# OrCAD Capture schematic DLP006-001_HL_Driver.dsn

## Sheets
1 P01- Title Page
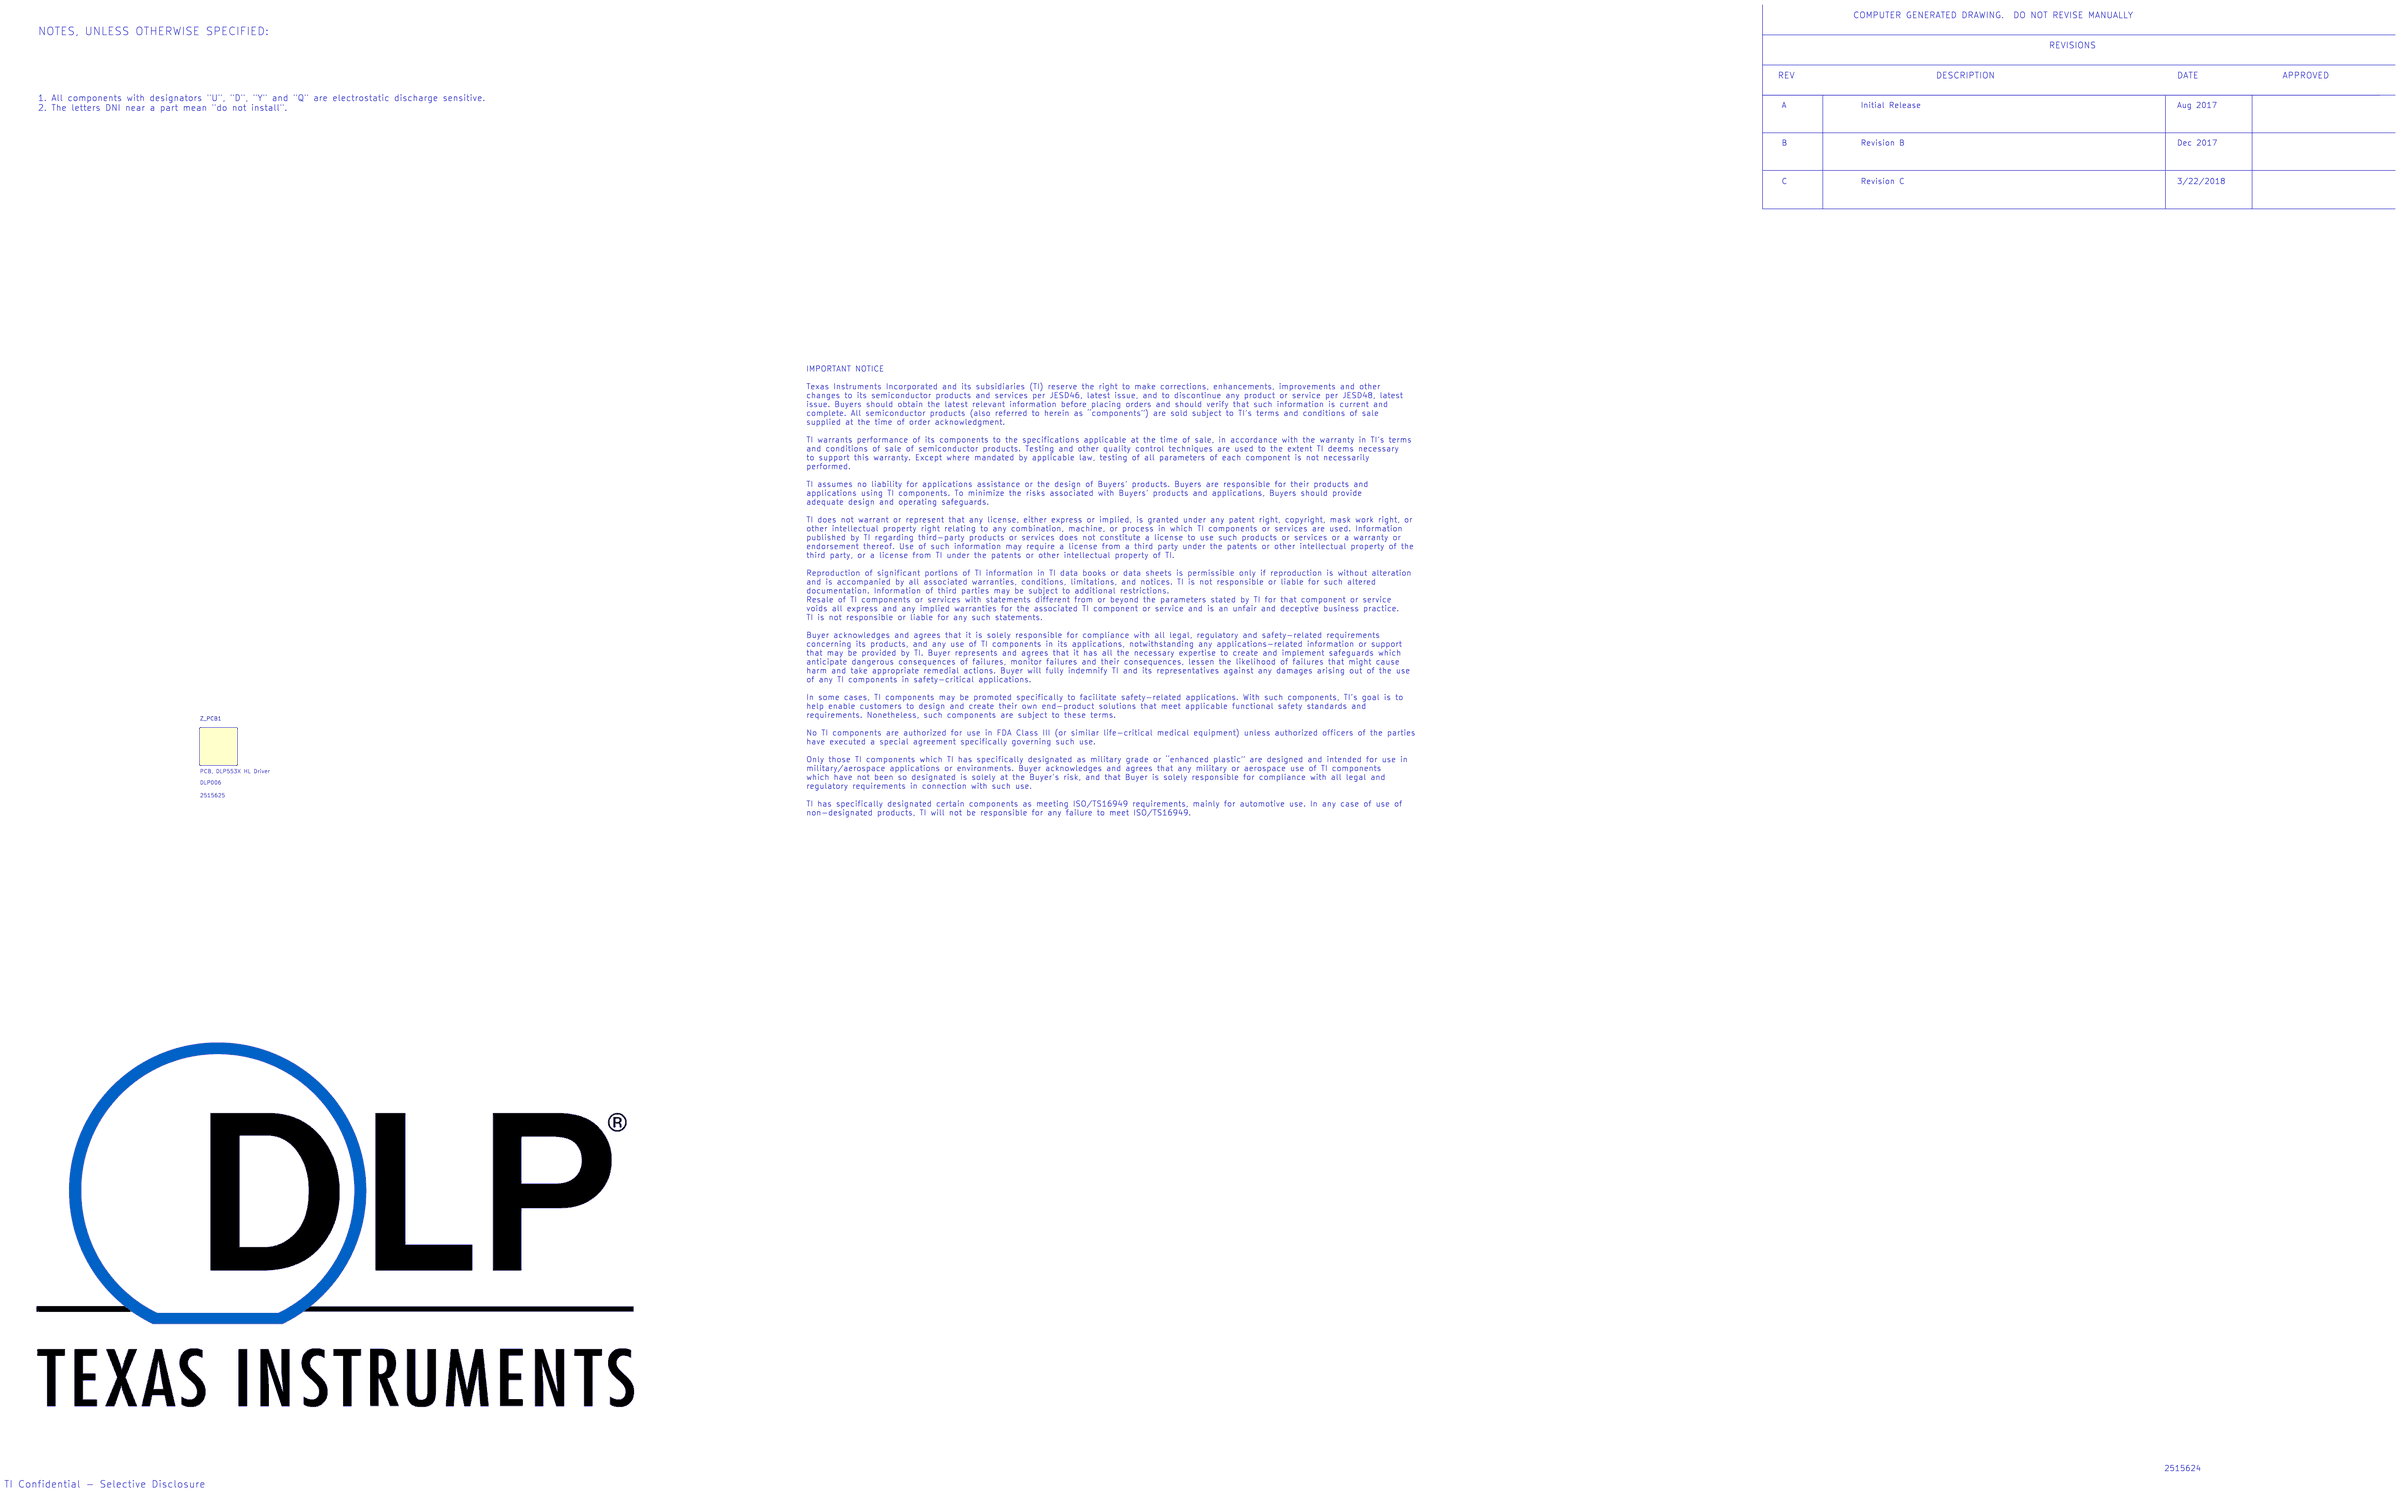
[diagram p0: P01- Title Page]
2 P02- Block Diagram: title: DLP5531-Q1 EVM Headlight Driver - DLP006; rev: C; note: 2515624
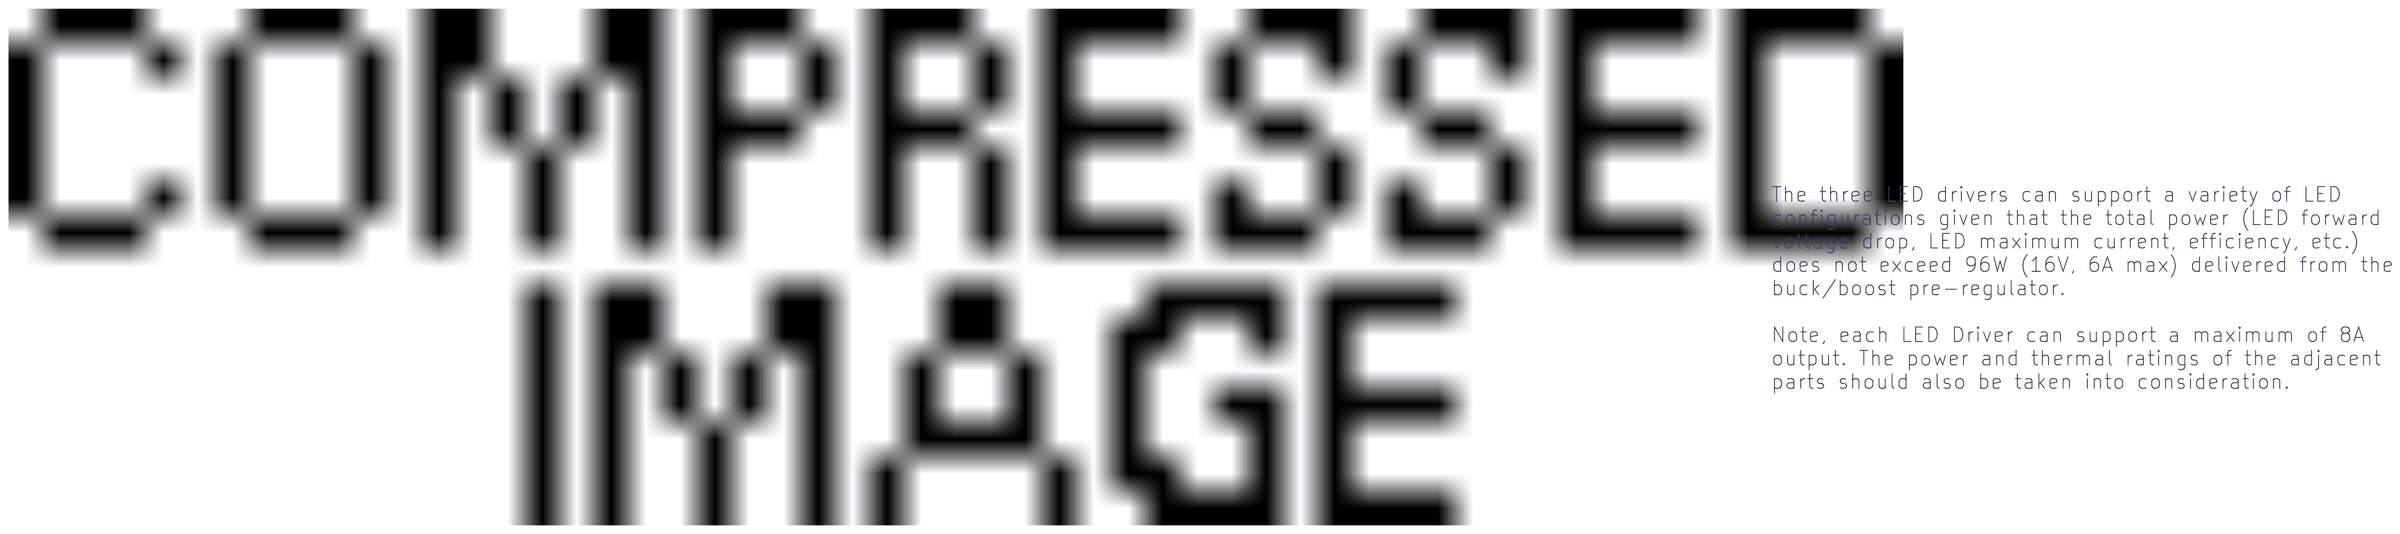
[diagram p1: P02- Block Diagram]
3 P03- LM5175 pre-regulator: size D; title: DLP5531-Q1 EVM Headlight Driver - DLP006; rev: C; note: 2515624
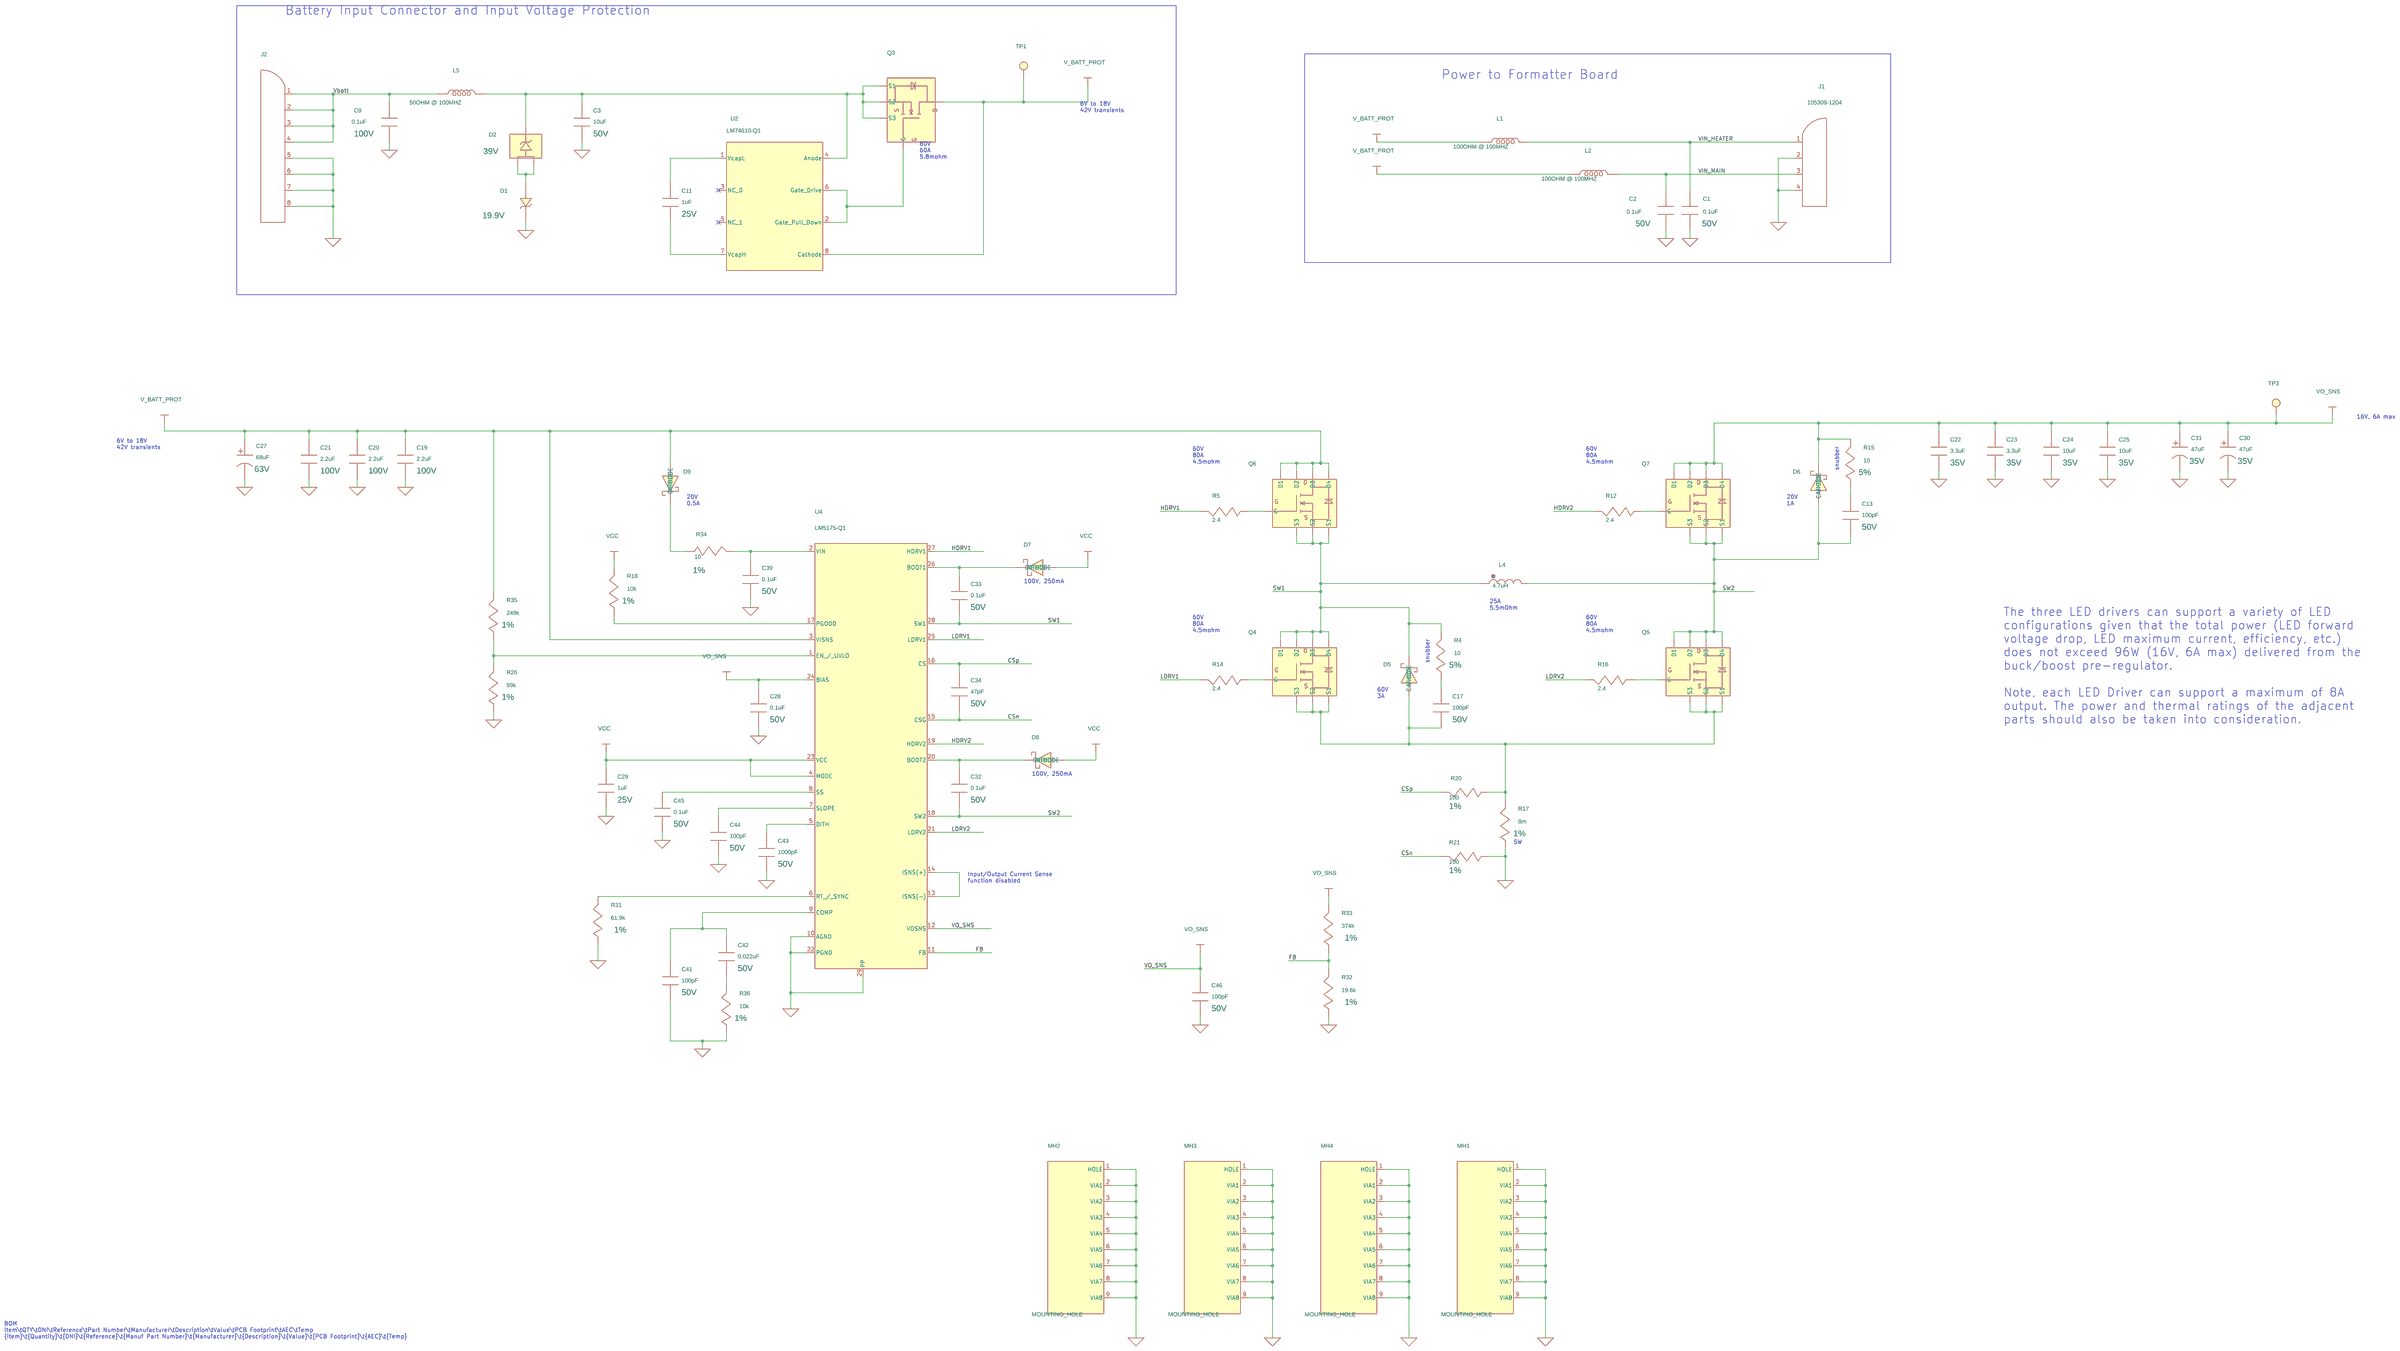
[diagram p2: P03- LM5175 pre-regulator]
4 P04- LM3409 LED drivers: size D; title: DLP5531-Q1 EVM Headlight Driver - DLP006; rev: C; note: 2515624
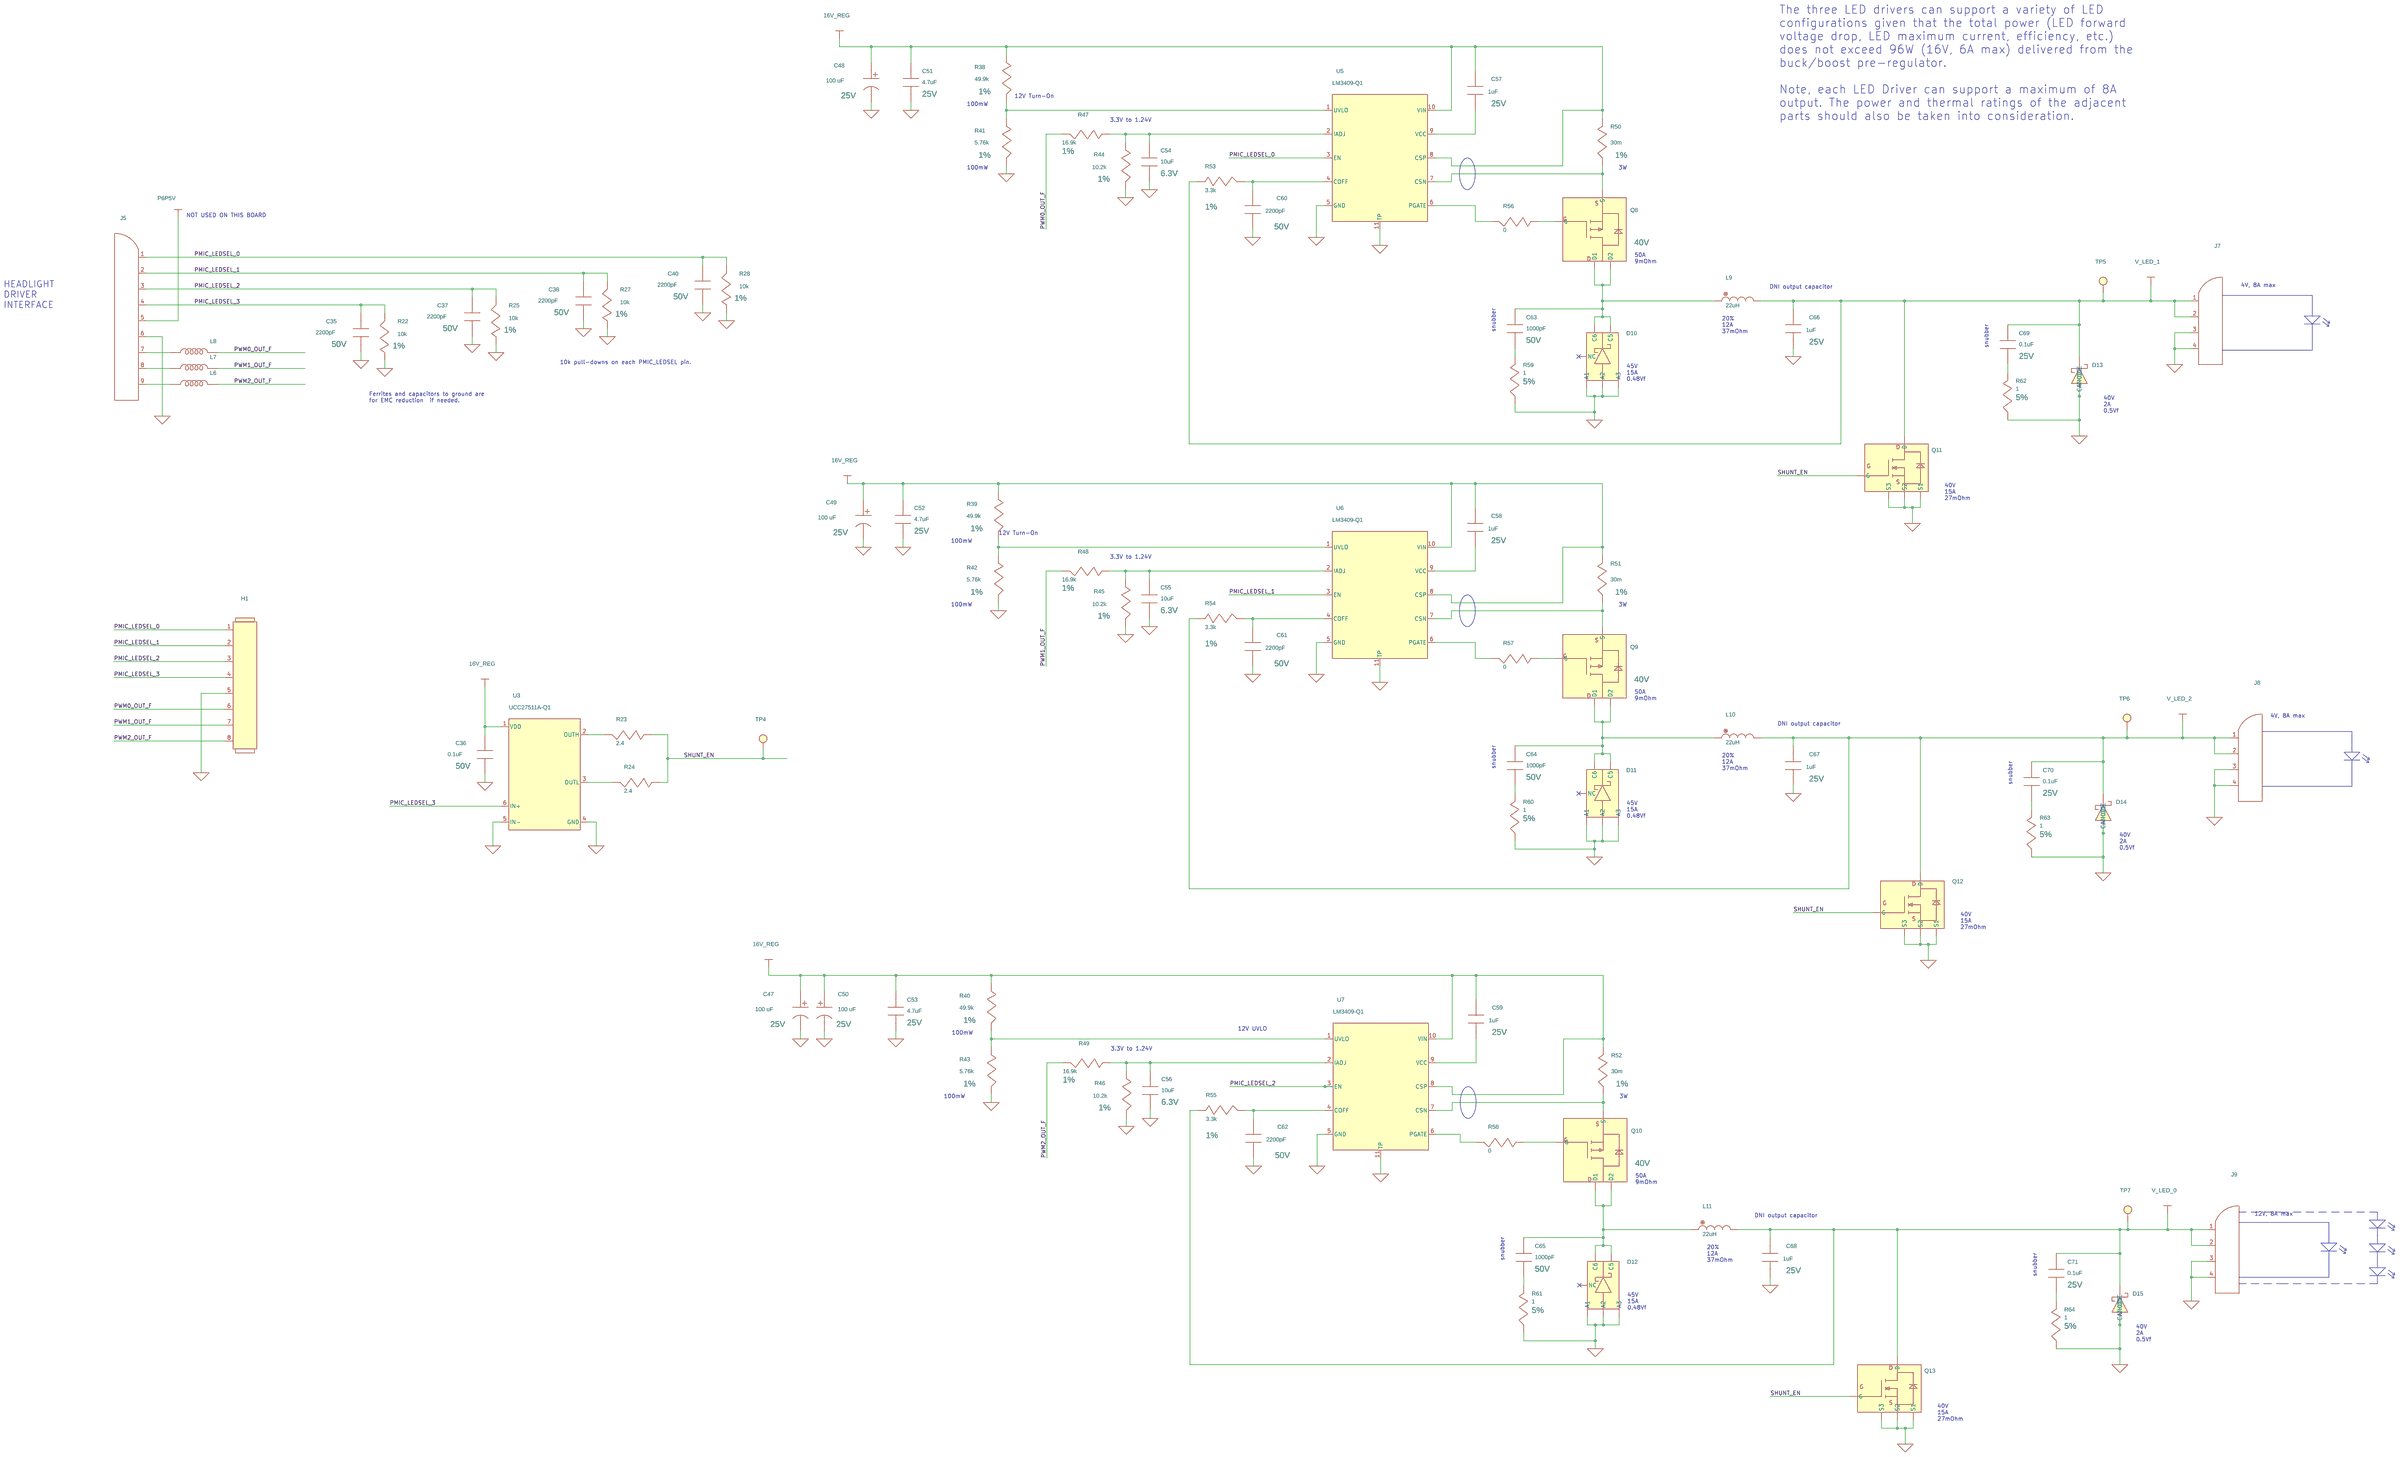
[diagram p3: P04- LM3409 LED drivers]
5 P05- LM25118 fan driver: size D; title: DLP5531-Q1 EVM Headlight Driver - DLP006; rev: C; note: 2515624
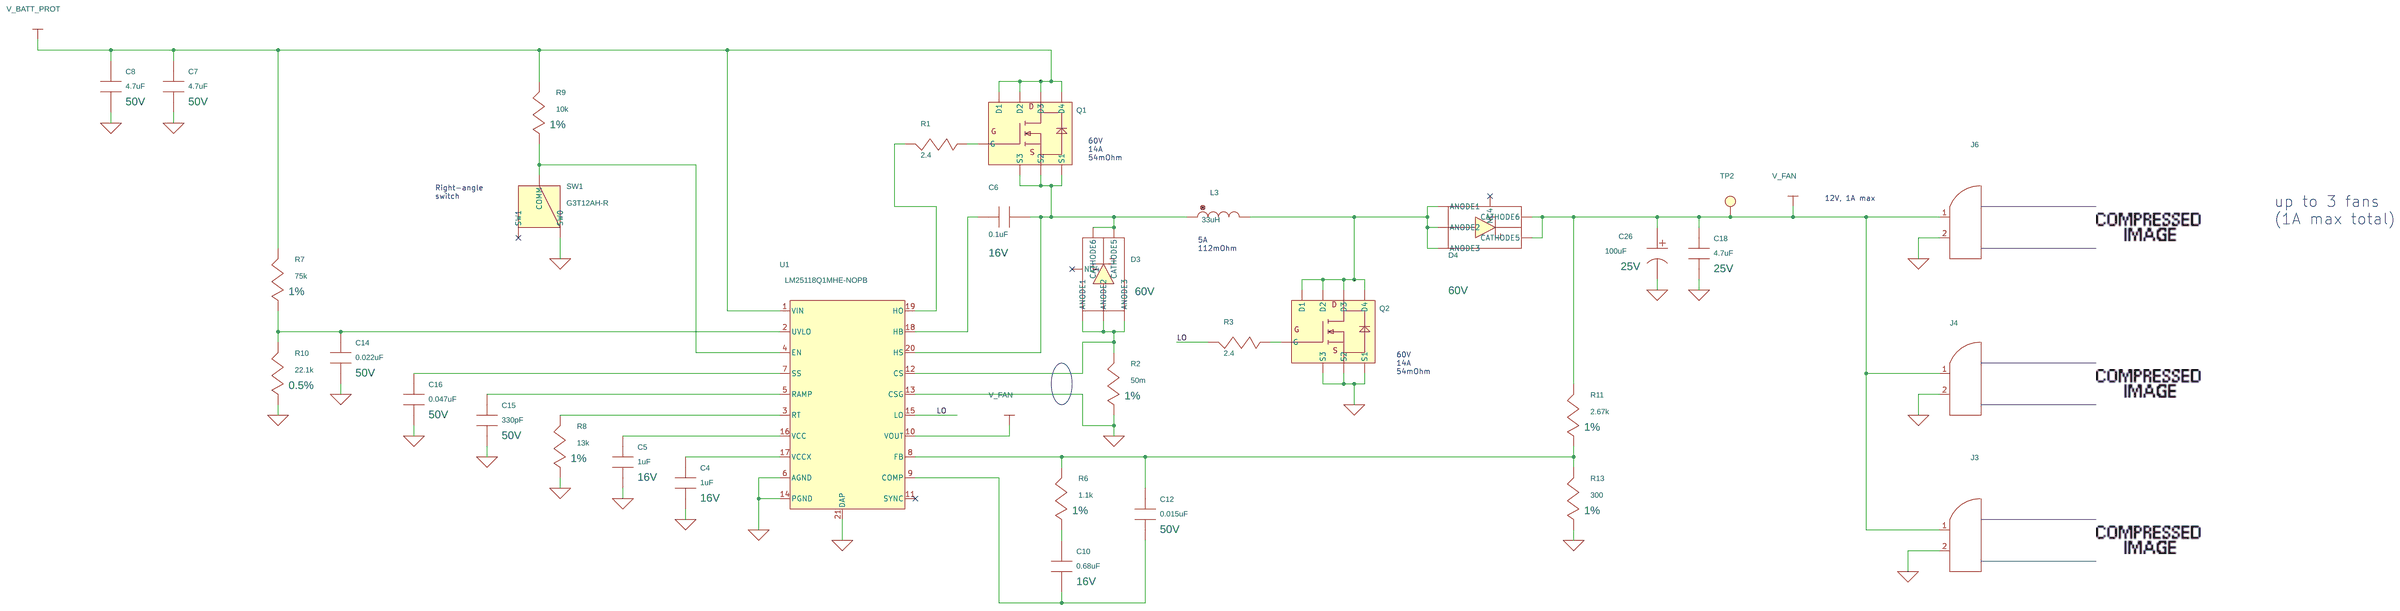
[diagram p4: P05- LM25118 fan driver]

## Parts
sheet P01- Title Page
Z_PCB1  PCB
sheet P03- LM5175 pre-regulator
C1  0.1uF  [C_0603]
C2  0.1uF  [C_0603]
C3  10uF  [C_1210]
C9  0.1uF  [C_0603]
C11  1uF  [C_0603]
C13  100pF  [C_0402]
C17  100pF  [C_0402]
C19  2.2uF  [C_1210]
C20  2.2uF  [C_1210]
C21  2.2uF  [C_1210]
C22  3.3uF  [C_0805]
C23  3.3uF  [C_0805]
C24  10uF  [C_1210]
C25  10uF  [C_1210]
C27  68uF  [CAL_ALUM_EEH-ZC1J680V]
C28  0.1uF  [C_0603]
C29  1uF  [C_0603]
C30  47uF  [CAP_ALUM_EEH-ZC1V470P]
C31  47uF  [CAP_ALUM_EEH-ZC1V470P]
C32  0.1uF  [C_0603]
C33  0.1uF  [C_0603]
C34  47pF  [C_0402]
C39  0.1uF  [C_0603]
C41  100pF  [C_0402]
C42  0.022uF  [C_0402]
C43  1000pF  [C_0402]
C44  100pF  [C_0402]
C45  0.1uF  [C_0603]
C46  100pF  [C_0402]
D1  PTVS17VS1UR,115  [SOD-123W_PTVS17VS1UR-115]
D2  LDP01-39AY  [D2PAK-3_LDP01-39AY]
D5  B360A-13-F  [SMA_B360A-13-F]
D6  SS12-E3/61T  [SMA-DO-214AC_SS12-E3-61T]
D7  BAT46WJ,115  [SOD-323-2_BAT46WJ-115]
D8  BAT46WJ,115  [SOD-323-2_BAT46WJ-115]
D9  MBR0520LT1G  [SOD-123_MBR0520LT1G]
J1  105309-1204  [CONN-4pos_105309-1204]
J2  105309-1208  [CONN-8pos_105309-1208]
L1  100OHM @ 100MHZ  [L_0805]
L2  100OHM @ 100MHZ  [L_0805]
L4  4.7uH  [Inductor_SRP1770TA-4R7M]
L5  50OHM @ 100MHZ  [L_1206]
MH1  MOUNTING_HOLE  [MH9-276-157]
MH2  MOUNTING_HOLE  [MH9-276-157]
MH3  MOUNTING_HOLE  [MH9-276-157]
MH4  MOUNTING_HOLE  [MH9-276-157]
Q3  SQJA80EP-T1_GE3  [PowerPAK-SO-8L-4_SQJA80EP]
Q4  DMT6007LFG-7  [PowerDI3333-8_DMT6007LFG-7]
Q5  DMT6007LFG-7  [PowerDI3333-8_DMT6007LFG-7]
Q6  DMT6007LFG-7  [PowerDI3333-8_DMT6007LFG-7]
Q7  DMT6007LFG-7  [PowerDI3333-8_DMT6007LFG-7]
R4  10  [R_0603]
R5  2.4  [R_0402]
R12  2.4  [R_0402]
R14  2.4  [R_0402]
R15  10  [R_0603]
R16  2.4  [R_0402]
R17  8m  [KOA_TLRH3APTTE8L00F]
R18  10k  [R_0402]
R20  100  [R_0402]
R21  100  [R_0402]
R26  59k  [R_0402]
R31  61.9k  [R_0402]
R32  19.6k  [R_0402]
R33  374k  [R_0402]
R34  10  [R_0402]
R35  249k  [R_0402]
R36  10k  [R_0402]
TP1  Probe-Testpoint  [TESTPOINT_S1751-46R]
TP3  Probe-Testpoint  [TESTPOINT_S1751-46R]
U2  LM74610-Q1  [VSSOP-8_LM74610QDGKTQ1]
U4  LM5175-Q1  [HTSSOP-28_LM5175QPWPTQ1]
sheet P04- LM3409 LED drivers
C35  2200pF  [C_0402]
C36  0.1uF  [C_0603]
C37  2200pF  [C_0402]
C38  2200pF  [C_0402]
C40  2200pF  [C_0402]
C47  100 uF  [CAP_ALUM_EEE-FK1E101SP]
C48  100 uF  [CAP_ALUM_EEE-FK1E101SP]
C49  100 uF  [CAP_ALUM_EEE-FK1E101SP]
C50  100 uF  [CAP_ALUM_EEE-FK1E101SP]
C51  4.7uF  [C_1206]
C52  4.7uF  [C_1206]
C53  4.7uF  [C_1206]
C54  10uF  [C_0805]
C55  10uF  [C_0805]
C56  10uF  [C_0805]
C57  1uF  [C_0402]
C58  1uF  [C_0402]
C59  1uF  [C_0402]
C60  2200pF  [C_0402]
C61  2200pF  [C_0402]
C62  2200pF  [C_0402]
C63  1000pF  [C_0402]
C64  1000pF  [C_0402]
C65  1000pF  [C_0402]
C66  1uF  [C_0603]
C67  1uF  [C_0603]
C68  1uF  [C_0603]
C69  0.1uF  [C_0402]
C70  0.1uF  [C_0402]
C71  0.1uF  [C_0402]
D10  NTS1545MFST1G  [SO-8-FL_NTS1545MFST1G]
D11  NTS1545MFST1G  [SO-8-FL_NTS1545MFST1G]
D12  NTS1545MFST1G  [SO-8-FL_NTS1545MFST1G]
D13  B240Q-13-F  [SMB-2_B240Q-13-F]
D14  B240Q-13-F  [SMB-2_B240Q-13-F]
D15  B240Q-13-F  [SMB-2_B240Q-13-F]
H1  68000-408HLF  [HEADER_68000-408HLF]
J5  501331-0907  [CONN-9pos_501331-0907]
J7  105309-1304  [CONN-4pos_105309-1304]
J8  105309-1304  [CONN-4pos_105309-1304]
J9  105309-1304  [CONN-4pos_105309-1304]
L6  120OHM @ 100MHZ  [L_0402]
L7  120OHM @ 100MHZ  [L_0402]
L8  120OHM @ 100MHZ  [L_0402]
L9  22uH  [Inductor_SRP1265A-220M]
L10  22uH  [Inductor_SRP1265A-220M]
L11  22uH  [Inductor_SRP1265A-220M]
Q8  IPD50P04P4-13  [TO-252-3_IPD50P04P4-13]
Q9  IPD50P04P4-13  [TO-252-3_IPD50P04P4-13]
Q10  IPD50P04P4-13  [TO-252-3_IPD50P04P4-13]
Q11  SQJ148EP-T1_GE3  [PowerPAK-SO-8L-4_SQJ148EP]
Q12  SQJ148EP-T1_GE3  [PowerPAK-SO-8L-4_SQJ148EP]
Q13  SQJ148EP-T1_GE3  [PowerPAK-SO-8L-4_SQJ148EP]
R22  10k  [R_0402]
R23  2.4  [R_0402]
R24  2.4  [R_0402]
R25  10k  [R_0402]
R27  10k  [R_0402]
R28  10k  [R_0402]
R38  49.9k  [R_0402]
R39  49.9k  [R_0402]
R40  49.9k  [R_0402]
R41  5.76k  [R_0402]
R42  5.76k  [R_0402]
R43  5.76k  [R_0402]
R44  10.2k  [R_0402]
R45  10.2k  [R_0402]
R46  10.2k  [R_0402]
R47  16.9k  [R_0402]
R48  16.9k  [R_0402]
R49  16.9k  [R_0402]
R50  30m  [R_2512]
R51  30m  [R_2512]
R52  30m  [R_2512]
R53  3.3k  [R_0402]
R54  3.3k  [R_0402]
R55  3.3k  [R_0402]
R56  0  [R_0402]
R57  0  [R_0402]
R58  0  [R_0402]
R59  1  [R_0402]
R60  1  [R_0402]
R61  1  [R_0402]
R62  1  [R_0402]
R63  1  [R_0402]
R64  1  [R_0402]
TP4  Probe-Testpoint  [TESTPOINT_S1751-46R]
TP5  Probe-Testpoint  [TESTPOINT_S1751-46R]
TP6  Probe-Testpoint  [TESTPOINT_S1751-46R]
TP7  Probe-Testpoint  [TESTPOINT_S1751-46R]
U3  UCC27511A-Q1  [SOT-23_UCC27511A-Q1]
U5  LM3409-Q1  [MSOP-10-PowerPAD_LM3409QMY-NOPB]
U6  LM3409-Q1  [MSOP-10-PowerPAD_LM3409QMY-NOPB]
U7  LM3409-Q1  [MSOP-10-PowerPAD_LM3409QMY-NOPB]
sheet P05- LM25118 fan driver
C4  1uF  [C_0603]
C5  1uF  [C_0603]
C6  0.1uF  [C_0402]
C7  4.7uF  [C_1206]
C8  4.7uF  [C_1206]
C10  0.68uF  [C_0603]
C12  0.015uF  [C_0402]
C14  0.022uF  [C_0402]
C15  330pF  [C_0402]
C16  0.047uF  [C_0603]
C18  4.7uF  [C_1206]
C26  100uF  [CAP_ALUM_EEE-FPE101XAP]
D3  NRVTS560EMFST1G  [SO-8_NRVTS560EMFST1G]
D4  NRVTS560EMFST1G  [SO-8_NRVTS560EMFST1G]
J3  105309-1202  [CONN-2pos_105309-1202]
J4  105309-1202  [CONN-2pos_105309-1202]
J6  105309-1202  [CONN-2pos_105309-1202]
L3  33uH  [Inductor_SRP1038A-330M]
Q1  BUK7M67-60EX  [LFPAK33-5_BUK7M67-60EX]
Q2  BUK7M67-60EX  [LFPAK33-5_BUK7M67-60EX]
R1  2.4  [R_0402]
R2  50m  [R_1206]
R3  2.4  [R_0402]
R6  1.1k  [R_0402]
R7  75k  [R_0402]
R8  13k  [R_0402]
R9  10k  [R_0402]
R10  22.1k  [R_0603]
R11  2.67k  [R_0402]
R13  300  [R_0402]
SW1  G3T12AH-R  [SWITCH_G3T12AH-R]
TP2  Probe-Testpoint  [TESTPOINT_S1751-46R]
U1  LM25118Q1MHE-NOPB  [HTSSOP-20_LM25118Q1MHE-NOPB]

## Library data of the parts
Z_PCB1 = PCB: PCB, DLP553X HL Driver; Alt Part Number: 2515625; Manuf Part Number: DLP006; Manufacturer: Any
C1 C2 C28 C32 C33 C36 C39 C45 = CAP_NP_dsize: CAP CER 0.1uF 10% 50V X7R 0603; AEC: AEC-Q200; Manuf Part Number: C0603C104K5RAC3190; Manufacturer: KEMET; Temp: -55 C to +125 C; Tolerance: 10%; VPC: 50V
C3 = CAP_NP_dsize: CAP CER 10uF 10% 50V X7S 1210; AEC: AEC-Q200; Manuf Part Number: CGA6P3X7S1H106K250AB; Manufacturer: TDK; Temp: -55 C to +125 C; Tolerance: 10%; VPC: 50V
C9 = CAP_NP_dsize: CAP CER 0.1uF 20% 100V X7R 0603; AEC: AEC-Q200; Manuf Part Number: CGA3E3X7S2A104M080AB; Manufacturer: TDK; Temp: -55 C to +125 C; Tolerance: 20%; VPC: 100V
C11 C29 = CAP_NP_dsize: CAP CER 1uF 10% 25V X7R 0603; AEC: AEC-Q200; Manuf Part Number: TMK107AB7105KAHT; Manufacturer: Taiyo Yuden; Temp: -55 C to +125 C; Tolerance: 10%; VPC: 25V
C13 C17 C41 C44 C46 = CAP_NP_dsize: CAP CER 100pF 10% 50V X7R 0402; AEC: AEC-Q200; Manuf Part Number: C0402C101K5RACAUTO; Manufacturer: KEMET; Temp: -55 C to +125 C; Tolerance: 10%; VPC: 50V
C19-C21 = CAP_NP_dsize: CAP CER 2.2uF 10% 100V X7R 1210; AEC: AEC-Q200; Manuf Part Number: HMK325B7225KMHT; Manufacturer: Taiyo Yuden; Temp: -55 C to +125 C; Tolerance: 10%; VPC: 100V
C22 C23 = CAP_NP_dsize: CAP CER 3.3uF 10% 35V X7R 0805; AEC: AEC-Q200; Manuf Part Number: CGA4J1X7R1V335K125AC; Manufacturer: TDK; Temp: -55 C to +125 C; Tolerance: 10%; VPC: 35V
C24 C25 = CAP_NP_dsize: CAP CER 10uF 10% 35V X7R 1210; AEC: AEC-Q200; Manuf Part Number: GMJ325KB7106KMHP; Manufacturer: Taiyo Yuden; Temp: -55 C to +125 C; Tolerance: 10%; VPC: 35V
C27 = CAP_POL_dsize: CAP ALUM 68uF 20% 63V 30mOhm; AEC: AEC-Q200; Manuf Part Number: EEH-ZC1J680V; Manufacturer: Panasonic; RATING/TOLERANCE: <RATING/TOLERANCE>; TOLERANCE: 20%; Temp: -55 C to +125 C; VPC: 63V
C30 C31 = CAP_POL_dsize: CAP ALUM 47uF 20% 35V 60mOhm; AEC: AEC-Q200; Manuf Part Number: EEH-ZC1V470P; Manufacturer: Panasonic; RATING/TOLERANCE: <RATING/TOLERANCE>; TOLERANCE: 20%; Temp: -55 C to +125 C; VPC: 35V
C34 = CAP_NP_dsize: CAP CER 47pF 5% 50V C0G (NP0) 0402; AEC: AEC-Q200; Manuf Part Number: AC0402JRNPO9BN470; Manufacturer: Yageo; Temp: -55 C to +125 C; Tolerance: 5%; VPC: 50V
C14 C42 = CAP_NP_dsize: CAP CER 0.022uF 10% 50V X7R 0402; AEC: AEC-Q200; Manuf Part Number: CGA2B3X7R1H223K050BB; Manufacturer: TDK; Temp: -55 C to +125 C; Tolerance: 10%; VPC: 50V
C43 C63-C65 = CAP_NP_dsize: CAP CER 1000pF 10% 50V X7R 0402; AEC: AEC-Q200; Manuf Part Number: AC0603KRX7R9BB102; Manufacturer: Yageo; Temp: -55 C to +125 C; Tolerance: 10%; VPC: 50V
D1 = DIODE_ZENER: TVS DIODE 19.9Vbreakdown 27.6Vclamp SOD-123W; AEC: AEC-Q101; ICA_MFR_NAME: Vishay; ICA_PARTNUM: $$2105147$$BZD27C10P; Manufacturer: Nexperia; Temp: -55 C to +150 C; VPC: 19.9V
D2 = DIODE_ZENER_0: TVS DIODE 39Vbreakdown 66Vclamp D2PAK-3; AEC: AEC-Q101; ICA_MFR_NAME: Vishay; ICA_PARTNUM: $$2105147$$BZD27C10P; Manufacturer: STMicroelectronics; Temp: -55 C to +175 C; VPC: 39V
D5 = DIODE_SCHOTTKY_dsize: Diode Schottky 60V 3A; AEC: AEC-Q101; Manufacturer: Diodes Inc; Temp: -55 C to +125 C; VPC: 60V
D6 = DIODE_SCHOTTKY_dsize: Diode Schottky 20V 1A; AEC: AEC-Q101; Manufacturer: Vishay; Temp: -65 C to +125 C; VPC: 20V
D7 D8 = DIODE_SCHOTTKY_dsize: Diode Schottky 100V 250mA; AEC: AEC-Q101; Manufacturer: Nexperia; Temp: -55 C to +150 C; VPC: 100V
D9 = DIODE_SCHOTTKY_dsize: Diode Schottky 20V 0.5A; AEC: AEC-Q101; Manufacturer: ON Semiconductor; Temp: -65 C to +125 C; VPC: 20V
J1 J7-J9 = CONN_1X4PINS_dsize: CONN 4POS 2.5MM VERT TH; Manufacturer: Molex; Temp: -40 C to +115 C
J2 = CONN_1X6PINS_dsize_0: CONN 8POS 2.5MM VERT TH; Manufacturer: Molex; Temp: -40 C to +115 C
L1 L2 = FERRITE_L: Ferrite 4A 100 Ohm @ 100MHz DCR 20mOhm 0805; AEC: AEC-Q200; CURRENT: 4A; ICA_MFR_NAME: STEWARD; ICA_PARTNUM: $$731362$$MI0603J680R-00; Manuf Part Number: MPZ2012S101ATD25; Manufacturer: TDK; Temp: -55 C to +155 C
L4 = L: Inductor 4.7uH shielded 25A 5.5mOhm; AEC: AEC-Q200; Manuf Part Number: SRP1770TA-4R7M; Manufacturer: Bourns; TOLERANCE: 20%; Temp: -40 C to +150 C
L5 = FERRITE_L_1: Ferrite 12A 50 Ohm @ 100MHz DCR 1.6mOhm 1206; AEC: AEC-Q200; CURRENT: 12A; ICA_MFR_NAME: STEWARD; ICA_PARTNUM: $$731362$$MI0603J680R-00; Manuf Part Number: BLM31SN500SZ1L; Manufacturer: Murata; Temp: -55 C to +125 C
MH1-MH4 = MOUNTING_HOLES_9_DSIZE_0: -- NOT A PART --; DNI: DNI; Manuf Part Number: -- NOT A PART --; Manufacturer: -- NOT A PART --
Q3 = NFET-DMN4800_5: MOSFET N-CH 80V 60A 5.8mohm PowerPAK SO-8L; AEC: AEC-Q101; Manufacturer: Vishay Siliconix; Temp: -55 C to +175 C
Q4-Q7 = NFET-DMN4800_3_v2: MOSFET N-channel 60V 80A 4.5mOhm PowerDI3333-8; AEC: AEC-Q200; Manufacturer: Diodes Inc; Temp: -55 C to +150 C; VPC: 60V
R4 R15 = RESISTOR_dsize: RES 10 ohm 5% 250mW 150V 0603; AEC: AEC-Q200; Manuf Part Number: ERJ-PA3J100V; Manufacturer: Panasonic; TOLERANCE: 5%; Temp: -55 C to +155 C; VPC: 150V
R1 R3 R5 R12 R14 R16 R23 R24 = RESISTOR_dsize: RES SMD 2.4 ohm 5% 100mW 0402; AEC: AEC-Q200; Manuf Part Number: ERJ-2GEJ2R4X; Manufacturer: Panasonic; TOLERANCE: 5%; Temp: -55 C to +155 C; VPC: 1/10W
R17 = RESISTOR_dsize: RES 8mOhm 1% 5W 2412; AEC: AEC-Q200; Manuf Part Number: TLRH3APTTE8L00F; Manufacturer: KOA Speer; TOLERANCE: 1%; Temp: -65 C to +170 C
R9 R18 R22 R25 R27 R28 R36 = RESISTOR_dsize: RES 10k 1% 100mW 50V 0402; AEC: AEC-Q200; Manuf Part Number: ERJ-2RKF1002X; Manufacturer: Panasonic; TOLERANCE: 1%; Temp: -55 C to +155 C; VPC: 50V
R20 R21 = RESISTOR_dsize: RES 100 ohm 1% 100mW 50V 0402; AEC: AEC-Q200; Manuf Part Number: ERJ-2RKF1002X; Manufacturer: Panasonic; TOLERANCE: 1%; Temp: -55 C to +155 C; VPC: 50V
R26 = RESISTOR_dsize: RES 59k 1% 100mW 50V 0402; AEC: AEC-Q200; Manuf Part Number: ERJ-2RKF5902X; Manufacturer: Panasonic; TOLERANCE: 1%; Temp: -55 C to +155 C; VPC: 50V
R31 = RESISTOR_dsize: RES 61.9k 1% 50V 100mW 0402; AEC: AEC-Q200; Manuf Part Number: ERJ-2RKF6192X; Manufacturer: Panasonic; TOLERANCE: 1%; Temp: -55 C to +155 C; VPC: 50V
R32 = RESISTOR_dsize: RES 19.6k 1% 50V 100mW 0402; AEC: AEC-Q200; Manuf Part Number: ERJ-2RKF1962X; Manufacturer: Panasonic; TOLERANCE: 1%; Temp: -55 C to +155 C; VPC: 50V
R33 = RESISTOR_dsize: RES 374k 1% 50V 100mW 0402; AEC: AEC-Q200; Manuf Part Number: ERJ-2RKF3743X; Manufacturer: Panasonic; TOLERANCE: 1%; Temp: -55 C to +155 C; VPC: 50V
R34 = RESISTOR_dsize: RES 10 ohm 1% 100mW 0402; AEC: AEC-Q200; Manuf Part Number: ERJ-2RKF10R0X; Manufacturer: Panasonic; TOLERANCE: 1%; Temp: -55 C to +155 C; VPC: 50V
R35 = RESISTOR_dsize: RES 249k 1% 100mW 50V 0402; AEC: AEC-Q200; Manuf Part Number: ERJ-2RKF2493X; Manufacturer: Panasonic; TOLERANCE: 1%; Temp: -55 C to +155 C; VPC: 50V
TP1-TP7 = Testpoint_0: TEST POINT TIN SMD; Manuf Part Number: S1751-46R; Manufacturer: Harwin; Temp: -55 C to +125 C
U2 = LM3409_SSOP_3: IC Reverse Polarity Protection; AEC: AEC-Q100; Manuf Part Number: LM74610QDGKTQ1; Manufacturer: Texas Instruments; Temp: -40 C to +125 C
U4 = LM25118Q1MHE_NOPB_5: LM5175 Synchronous Buck-Boost Controller; AEC: AEC-Q100; Manuf Part Number: LM5175QPWPTQ1; Manufacturer: Texas Instruments; Temp: -40 C to +125 C
C35 C37 C38 C40 C60-C62 = CAP_NP_dsize: CAP CER 2200pF 10% 50V X7R 0402; AEC: AEC-Q200; Manuf Part Number: CGA2B2X7R1H222K050BA; Manufacturer: TDK; Temp: -55 C to +125 C; Tolerance: 10%; VPC: 50V
C47-C50 = CAP_POL_dsize: CAP ALUM 100uF 20% 25V 360mOhm; AEC: AEC-Q200; Manuf Part Number: EEE-FK1E101SP; Manufacturer: Panasonic; RATING/TOLERANCE: <RATING/TOLERANCE>; TOLERANCE: 20%; Temp: -55 C to +105 C; VPC: 25V
C18 C51-C53 = CAP_NP_dsize: CAP CER 4.7uF 10% 25V X7R 1206; AEC: AEC-Q200; Manuf Part Number: TMK316AB7475KLHT; Manufacturer: Taiyo Yuden; Temp: -55 C to +125 C; Tolerance: 10%; VPC: 25V
C54-C56 = CAP_NP_dsize: CAP CER 10uF 6.3V X7R 10% 0805; AEC: AEC-Q200; Manuf Part Number: CGA4J1X7R0J106K125AC; Manufacturer: TDK; Temp: -55 C to +125 C; Tolerance: 10%; VPC: 6.3V
C57-C59 = CAP_NP_dsize: CAP CER 1uF 20% 25V X6S 0402; AEC: AEC-Q200; Manuf Part Number: TMK105AC6105MV-F; Manufacturer: Taiyo Yuden; Temp: -55 C to +105 C; Tolerance: 20%; VPC: 25V
C66-C68 = CAP_NP_dsize: CAP CER 1uF 10% 25V X7R 0603; AEC: AEC-Q200; DNI: DNI; Manuf Part Number: TMK107AB7105KAHT; Manufacturer: Taiyo Yuden; Temp: -55 C to +125 C; Tolerance: 10%; VPC: 25V
C69-C71 = CAP_NP_dsize: CAP CER 0.1uF 10% 25V X7R 0402; AEC: AEC-Q200; Manuf Part Number: GCM155R71E104KE02D; Manufacturer: Murata; Temp: -55 C to +125 C; Tolerance: 10%; VPC: 25V
D10-D12 = DIODE_SCHOTTKY_dsize_8: Diode 45V 15A 480mVf; AEC: AEC-Q101; Manufacturer: ON Semiconductor; Temp: -55 C to +150 C; VPC: 45V
D13-D15 = DIODE_SCHOTTKY_dsize: Diode 40V 2A 500mVf; AEC: AEC-Q101; Manufacturer: Diodes Inc; Temp: -65 C to +150 C; VPC: 40V
H1 = HEADER_1X8_H_dsize_0: CONN HEADER 8POS .100 STR TIN; Manufacturer: Amphenol FCI; Temp: -65 C to +130 C
J5 = CONN_1X9PINS_dsize: CONN 9POS 1MM VERT SMD; Manufacturer: Molex; Temp: -40 C to +105 C
L6-L8 = FERRITE_L_0: Ferrite 400mA 120 Ohm @ 100MHz DCR 180mOhm 0402; AEC: AEC-Q200; CURRENT: 200mA; ICA_MFR_NAME: STEWARD; ICA_PARTNUM: $$731362$$MI0603J680R-00; Manuf Part Number: MMZ1005Y121CTD25; Manufacturer: TDK; Temp: -55 C to +125 C
L9-L11 = L: Inductor 22uH 20% 12A 37mOhm SMD; AEC: AEC-Q200; Manuf Part Number: SRP1265A-220M; Manufacturer: Bourns; TOLERANCE: 20%; Temp: -40 C to +150 C
Q8-Q10 = PFET-POWERD-TSOP6_6: MOSFET P-Channel 40V 50A 9mOhm DPAK-2; AEC: AEC-Q101; Manufacturer: Infineon Technologies; Temp: -55 C to +175 C; VPC: 40V
Q11-Q13 = NFET-DMN4800_4: MOSFET N-CH 40V 15A 27mOhm SO-8L-4; AEC: AEC-Q101; Manufacturer: Vishay Siliconix; Temp: -55 C to +175 C
R38-R40 = RESISTOR_dsize: RES 49.9k 1% 100mW 0402; AEC: AEC-Q200; Manuf Part Number: ERJ-2RKF4992X; Manufacturer: Panasonic; TOLERANCE: 1%; Temp: -55 C to +155 C; VPC: 50V
R41-R43 = RESISTOR_dsize: RES 5.76k 1% 100mW 0402; AEC: AEC-Q200; Manuf Part Number: ERJ-2RKF5761X; Manufacturer: Panasonic; TOLERANCE: 1%; Temp: -55 C to +155 C; VPC: 50V
R44-R46 = RESISTOR_dsize: RES 10.2k ohm 100mW 1% 0402 SMD; AEC: AEC-Q200; Manuf Part Number: ERJ-2RKF1022X; Manufacturer: Panasonic; TOLERANCE: 1%; Temp: -55 C to +155 C; VPC: 1/10W
R47-R49 = RESISTOR_dsize: RES 16.9k ohm 100mW 1% 0402 SMD; AEC: AEC-Q200; Manuf Part Number: ERJ-2RKF1692X; Manufacturer: Panasonic; TOLERANCE: 1%; Temp: -55 C to +155 C; VPC: 1/10W
R50-R52 = RESISTOR_dsize: RES 30mOhm 1% 3W; AEC: AEC-Q200; Manuf Part Number: CRA2512-FZ-R030ELF; Manufacturer: Bourns; TOLERANCE: 1%; Temp: -55 C to +170 C
R53-R55 = RESISTOR_dsize: RES 3.3k 1% 100mW 0402; AEC: AEC-Q200; Manuf Part Number: ERJ-2RKF3301X; Manufacturer: Panasonic; TOLERANCE: 1%; Temp: -55 C to +155 C; VPC: 50V
R56-R58 = RESISTOR_dsize: RES SMD 0 ohm 5% 1/16W 0402; AEC: AEC-Q200; Manuf Part Number: AF0402JR-070RL; Manufacturer: Yageo; TOLERANCE: 5%; Temp: -55 C to +155 C; VPC: 1/16W
R59-R64 = RESISTOR_dsize: RES 1 ohm 5% 200mW 0402; AEC: AEC-Q200; Manuf Part Number: RCS04021R00JNED; Manufacturer: Vishay; TOLERANCE: 5%; Temp: -55 C to +155 C; VPC: 50V
U3 = LM3409_SSOP_6: IC Gate Driver; AEC: AEC-Q100; Manuf Part Number: UCC27511AQDBVRQ1; Manufacturer: Texas Instruments; Temp: -40 C to +140 C
U5-U7 = LM3409_SSOP_2: IC P-FET Buck Controller; AEC: AEC-Q100; Manuf Part Number: LM3409QMY-NOPB; Manufacturer: Texas Instruments; Temp: -40 C to +125 C
C4 C5 = CAP_NP_dsize: CAP CER 1uF 10% 16V X7R 0603; AEC: AEC-Q200; Manuf Part Number: CGA3E1X7R1C105K080AC; Manufacturer: TDK; Temp: -55 C to +125 C; Tolerance: 10%; VPC: 16V
C6 = CAP_NP_dsize: CAP CER 0.1uF 10% 16V X7R 0402; AEC: AEC-Q200; Manuf Part Number: C0402C104K4RACAUTO; Manufacturer: KEMET; Temp: -55 C to +125 C; Tolerance: 10%; VPC: 16V
C7 C8 = CAP_NP_dsize: CAP CER 4.7uF 10% 50V X7S 1206; AEC: AEC-Q200; Manuf Part Number: UMK316AC7475KLHTE; Manufacturer: Taiyo Yuden; Temp: -55 C to +125 C; Tolerance: 10%; VPC: 50V
C10 = CAP_NP_dsize: CAP CER 0.68uF 20% 16V X7R 0603; AEC: AEC-Q200; Manuf Part Number: CGA3E1X7R1C684M080AC; Manufacturer: TDK; Temp: -55 C to +125 C; Tolerance: 20%; VPC: 16V
C12 = CAP_NP_dsize: CAP CER 0.015uF 20% 50V X7R 0402; AEC: AEC-Q200; Manuf Part Number: CGA2B3X7R1H153M050BB; Manufacturer: TDK; Temp: -55 C to +125 C; Tolerance: 20%; VPC: 50V
C15 = CAP_NP_dsize: CAP CER 330pF 5% 50V C0G (NP0) 0402; AEC: AEC-Q200; Manuf Part Number: CGA2B2C0G1H331J050BA; Manufacturer: TDK; Temp: -55 C to +125 C; Tolerance: 5%; VPC: 50V
C16 = CAP_NP_dsize: CAP CER 0.047uF 10% 50V X7R 0603; AEC: AEC-Q200; Manuf Part Number: 06035C473K4T2A; Manufacturer: AVX; Temp: -55 C to +125 C; Tolerance: 10%; VPC: 50V
C26 = CAP_POL_dsize: CAP ALUM 100uF 20% 25V 160mOhm; AEC: AEC-Q200; Manuf Part Number: EEE-FPE101XAP; Manufacturer: Panasonic; RATING/TOLERANCE: <RATING/TOLERANCE>; TOLERANCE: 20%; Temp: -55 C to +105 C; VPC: 25V
D3 D4 = DIODE_SCHOTTKY_dsize_12: Diode Schottky 5A 60V; AEC: AEC-Q101; Manufacturer: ON Semiconductor; Temp: -65 C to +175 C; VPC: 60V
J3 J4 J6 = CONN_1X4PINS_dsize_2: CONN 2POS 2.5MM VERT TH; Manufacturer: Molex; Temp: -40 C to +115 C
L3 = L: Inductor Shielded 33uH 20% 5A; AEC: AEC-Q200; Manuf Part Number: SRP1038A-330M; Manufacturer: Bourns; TOLERANCE: 20%; Temp: -40 C to +150 C
Q1 Q2 = NFET-DMN4800_3_v2: MOSFET N-Channel 60V 14A 54mOhm LFPAK33-5; AEC: AEC-Q101; Manufacturer: Nexperia; Temp: -55 C to +175 C
R2 = RESISTOR_dsize: RES 50mOhm 1% 1W 1206; AEC: AEC-Q200; Manuf Part Number: ERJ-8CWFR050V; Manufacturer: Panasonic; TOLERANCE: 1%; Temp: -55 C to +125 C
R6 = RESISTOR_dsize: RES 1.1k 1% 100mW 50V 0402; AEC: AEC-Q200; Manuf Part Number: ERJ-2RKF1101X; Manufacturer: Panasonic; TOLERANCE: 1%; Temp: -55 C to +155 C; VPC: 50V
R7 = RESISTOR_dsize: RES 75k 1% 100mW 50V 0402; AEC: AEC-Q200; Manuf Part Number: ERJ-2RKF7502X; Manufacturer: Panasonic; TOLERANCE: 1%; Temp: -55 C to +155 C; VPC: 50V
R8 = RESISTOR_dsize: RES 13k 1% 100mW 50V 0402; AEC: AEC-Q200; Manuf Part Number: ERJ-2RKF1302X; Manufacturer: Panasonic; TOLERANCE: 1%; Temp: -55 C to +155 C; VPC: 50V
R10 = RESISTOR_dsize: RES 22.1k 0.5% 100mW 100V 0603; AEC: AEC-Q200; Manuf Part Number: RG1608P-2212-D-T5; Manufacturer: Susumu; TOLERANCE: 0.5%; Temp: -55 C to +155 C; VPC: 100V
R11 = RESISTOR_dsize: RES 2.67k 1% 100mW 50V 0402; AEC: AEC-Q200; Manuf Part Number: RK73H1ETTP2671F; Manufacturer: KOA Speer; TOLERANCE: 1%; Temp: -55 C to +155 C; VPC: 50V
R13 = RESISTOR_dsize: RES 300 ohm 1% 100mW 50V; AEC: AEC-Q200; Manuf Part Number: ERJ-2RKF3000X; Manufacturer: Panasonic; TOLERANCE: 1%; Temp: -55 C to +155 C; VPC: 50V
SW1 = SW_SPST_1_dsize_5: SWITCH, SPDT, 28V, 100mA; Manufacturer: NKK Switches; Temp: -30 C to +85 C
U1 = LM25118Q1MHE_NOPB_4_v2: IC REG CTRLR Buck Boost; AEC: AEC-Q100; Manufacturer: Texas Instruments; Temp: -40 C to +125 C

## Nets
16V_REG: C22.2 C23.2 C24.2 C25.2 C28.2 C30.1 C31.1 C36.2 C46.2 C47.1 C48.1 C49.1 C50.1 C51.2 C52.2 C53.2 C57.2 C58.2 C59.2 D6.C(CATHODE) Q7.5(D1) Q7.6(D2) Q7.7(D3) Q7.8(D4) R15.1 R33.1 R38.2 R39.2 R40.2 R50.2 R51.2 R52.2 TP3.1(tp) U3.1(VDD) U4.12(VOSNS) U4.24(BIAS) U5.8(CSP) U5.10(VIN) U6.8(CSP) U6.10(VIN) U7.8(CSP) U7.10(VIN)
GND_SIGNAL: C1.1 C2.1 C3.1 C4.1 C5.1 C7.1 C8.1 C9.1 C14.1 C15.1 C16.1 C18.1 C19.1 C20.1 C21.1 C22.1 C23.1 C24.1 C25.1 C26.2 C27.2 C28.1 C29.1 C30.2 C31.2 C35.1 C36.1 C37.1 C38.1 C39.1 C40.1 C41.1 C43.1 C44.1 C45.1 C46.1 C47.2 C48.2 C49.2 C50.2 C51.1 C52.1 C53.1 C54.1 C55.1 C56.1 C60.1 C61.1 C62.1 C66.1 C67.1 C68.1 D1.1(CATHODE) D10.1(A1) D10.2(A2) D10.3(A3) D11.1(A1) D11.2(A2) D11.3(A3) D12.1(A1) D12.2(A2) D12.3(A3) D13.A(ANODE) D14.A(ANODE) D15.A(ANODE) H1.5 J1.2 J1.4 J2.5 J2.6 J2.7 J2.8 J3.2 J4.2 J5.6 J6.2 J7.3 J7.4 J8.3 J8.4 J9.3 J9.4 MH1.1(HOLE) MH1.2(VIA1) MH1.3(VIA2) MH1.4(VIA3) MH1.5(VIA4) MH1.6(VIA5) MH1.7(VIA6) MH1.8(VIA7) MH1.9(VIA8) MH2.1(HOLE) MH2.2(VIA1) MH2.3(VIA2) MH2.4(VIA3) MH2.5(VIA4) MH2.6(VIA5) MH2.7(VIA6) MH2.8(VIA7) MH2.9(VIA8) MH3.1(HOLE) MH3.2(VIA1) MH3.3(VIA2) MH3.4(VIA3) MH3.5(VIA4) MH3.6(VIA5) MH3.7(VIA6) MH3.8(VIA7) MH3.9(VIA8) MH4.1(HOLE) MH4.2(VIA1) MH4.3(VIA2) MH4.4(VIA3) MH4.5(VIA4) MH4.6(VIA5) MH4.7(VIA6) MH4.8(VIA7) MH4.9(VIA8) Q2.1(S1) Q2.2(S2) Q2.3(S3) Q11.1(S1) Q11.2(S2) Q11.3(S3) Q12.1(S1) Q12.2(S2) Q12.3(S3) Q13.1(S1) Q13.2(S2) Q13.3(S3) R2.2 R8.2 R10.2 R13.2 R17.2 R21.2 R22.2 R25.2 R26.2 R27.2 R28.2 R31.2 R32.2 R36.2 R41.1 R42.1 R43.1 R44.1 R45.1 R46.1 R59.1 R60.1 R61.1 R62.1 R63.1 R64.1 SW1.6(SW0) U1.6(AGND) U1.13(CSG) U1.14(PGND) U1.21(DAP) U3.4(GND) U3.5(IN-) U4.10(AGND) U4.22(PGND) U4.29(PP) U5.5(GND) U5.11(TP) U6.5(GND) U6.11(TP) U7.5(GND) U7.11(TP)
Vbatt: C9.2 J2.1 J2.2 J2.3 J2.4 L5.2
VCC: C29.2 D7.A(ANODE) D8.A(ANODE) R18.1 U4.4(MODE) U4.23(VCC)
VIN_HEATER: C1.2 J1.1 L1.1
VIN_MAIN: C2.2 J1.3 L2.1
CSn: C34.1 R21.1 U4.15(CSG)
CSp: C34.2 R20.1 U4.16(CS)
FB: R32.1 R33.2 U4.11(FB)
HDRV1: R5.1 U4.27(HDRV1)
HDRV2: R12.1 U4.19(HDRV2)
LDRV1: R14.1 U4.25(LDRV1)
LDRV2: R16.1 U4.21(LDRV2)
LO: R3.1 U1.15(LO)
P6P5V: J5.5
PMIC_LEDSEL_0: C40.2 H1.1 J5.1 R28.1 U5.3(EN)
PMIC_LEDSEL_1: C38.2 H1.2 J5.2 R27.1 U6.3(EN)
PMIC_LEDSEL_2: C37.2 H1.3 J5.3 R25.1 U7.3(EN)
PMIC_LEDSEL_3: C35.2 H1.4 J5.4 R22.1 U3.6(IN+)
PWM0_OUT_F: H1.6 L8.2 R47.1
PWM1_OUT_F: H1.7 L7.2 R48.1
PWM2_OUT_F: H1.8 L6.2 R49.1
SHUNT_EN: Q11.4(G) Q12.4(G) Q13.4(G) R23.2 R24.2 TP4.1(tp)
SW1: C33.1 D5.C(CATHODE) L4.1 Q4.5(D1) Q4.6(D2) Q4.7(D3) Q4.8(D4) Q6.1(S1) Q6.2(S2) Q6.3(S3) R4.1 U4.28(SW1)
SW2: C13.1 C32.1 D6.A(ANODE) L4.2 Q5.5(D1) Q5.6(D2) Q5.7(D3) Q5.8(D4) Q7.1(S1) Q7.2(S2) Q7.3(S3) U4.18(SW2)
V_BATT_PROT: C7.2 C8.2 C19.2 C20.2 C21.2 C27.1 D9.A(ANODE) L1.2 L2.2 Q1.5(D1) Q1.6(D2) Q1.7(D3) Q1.8(D4) Q3.5 Q6.5(D1) Q6.6(D2) Q6.7(D3) Q6.8(D4) R7.1 R9.1 R35.1 TP1.1(tp) U1.1(VIN) U2.8(Cathode) U4.3(VISNS)
V_FAN: C18.2 C26.1 D4.5(CATHODE5) D4.6(CATHODE6) J3.1 J4.1 J6.1 R11.1 TP2.1(tp) U1.10(VOUT)
V_LED_0: C68.2 C71.2 D15.C(CATHODE) J9.1 J9.2 L11.2 Q13.5(D) R55.2 TP7.1(tp)
V_LED_1: C66.2 C69.2 D13.C(CATHODE) J7.1 J7.2 L9.2 Q11.5(D) R53.2 TP5.1(tp)
V_LED_2: C67.2 C70.2 D14.C(CATHODE) J8.1 J8.2 L10.2 Q12.5(D) R54.2 TP6.1(tp)
N56946: R38.1 R41.2 U5.1(UVLO)
N57442: C60.2 R53.1 U5.4(COFF)
N57562: C57.1 U5.9(VCC)
N57763: Q8.3(S) R50.1 U5.7(CSN)
N57852: R56.1 U5.6(PGATE)
N60750: R39.1 R42.2 U6.1(UVLO)
N60866: C61.2 R54.1 U6.4(COFF)
N60906: C58.1 U6.9(VCC)
N60948: Q9.3(S) R51.1 U6.7(CSN)
N61008: R57.1 U6.6(PGATE)
N64164: R40.1 R43.2 U7.1(UVLO)
N64276: C62.2 R55.1 U7.4(COFF)
N64324: C59.1 U7.9(VCC)
N64418: Q10.3(S) R52.1 U7.7(CSN)
N64426: R58.1 U7.6(PGATE)
N66768: C39.2 R34.1 U4.2(VIN)
N66777: D9.C(CATHODE) R34.2
N67488: C44.2 U4.7(SLOPE)
N67495: C43.2 U4.5(DITH)
N67553: R26.1 R35.2 U4.1(EN_/_UVLO)
N67657: R18.2 U4.17(PGOOD)
N68022: C41.2 C42.2 U4.9(COMP)
N68052: C42.1 R36.1
N68109: R31.1 U4.6(RT_/_SYNC)
N68463: C33.2 D7.C(CATHODE) U4.26(BOOT1)
N68698: C32.2 D8.C(CATHODE) U4.20(BOOT2)
N69433: Q6.4(G) R5.2
N70256: Q4.4(G) R14.2
N70284: C17.1 D5.A(ANODE) Q4.1(S1) Q4.2(S2) Q4.3(S3) Q5.1(S1) Q5.2(S2) Q5.3(S3) R17.1 R20.2
N70639: Q7.4(G) R12.2
N70965: C17.2 R4.2
N71936: C13.2 R15.2
N87249: C14.2 R7.2 R10.1 U1.2(UVLO)
N87366: C16.2 U1.7(SS)
N87373: C15.2 U1.5(RAMP)
N87380: R8.1 U1.3(RT)
N87387: C5.2 U1.16(VCC)
N87394: C4.2 U1.17(VCCX)
N87932: C6.1 D3.5(CATHODE5) D3.6(CATHODE6) L3.1 Q1.1(S1) Q1.2(S2) Q1.3(S3) U1.20(HS)
N88013: R1.1 U1.19(HO)
N88019: C6.2 U1.18(HB)
N88053: D3.1(ANODE1) D3.2(ANODE2) D3.3(ANODE3) R2.1 U1.12(CS)
N88776: D4.1(ANODE1) D4.2(ANODE2) D4.3(ANODE3) L3.2 Q2.5(D1) Q2.6(D2) Q2.7(D3) Q2.8(D4)
N88824: Q2.4(G) R3.2
N88961: C12.2 R6.1 R11.2 R13.1 U1.8(FB)
N89225: C10.1 C12.1 U1.9(COMP)
N89343: C10.2 R6.2
N14686613: Q5.4(G) R16.2
N14713667: Q3.4(G) U2.2(Gate_Pull_Down) U2.6(Gate_Drive)
N14713719: C3.2 D2.1(CATHODE) L5.1 Q3.1(S1) Q3.2(S2) Q3.3(S3) U2.4(Anode)
N14713759: C11.1 U2.7(VcapH)
N14725098: C54.2 R44.2 R47.2 U5.2(IADJ)
N14726673: C55.2 R45.2 R48.2 U6.2(IADJ)
N14726919: C56.2 R46.2 R49.2 U7.2(IADJ)
N14728608: C63.2 D10.5(C5) D10.6(C6) L9.1 Q8.2(D2) Q8.tab(D1)
N14729090: C64.2 D11.5(C5) D11.6(C6) L10.1 Q9.2(D2) Q9.tab(D1)
N14729291: C65.2 D12.5(C5) D12.6(C6) L11.1 Q10.2(D2) Q10.tab(D1)
N14733774: R24.1 U3.3(OUTL)
N14733778: R23.1 U3.2(OUTH)
N14755460: C11.2 U2.1(VcapL)
N14772112: D1.2(ANODE) D2.2(ANODE1) D2.3(ANODE2)
N14778799: R9.2 SW1.5(COMM) U1.4(EN)
N14789264: C65.1 R61.2
N14790575: C63.1 R59.2
N14791153: C64.1 R60.2
N14801227: C71.1 R64.2
N14802192: U4.13(ISNS(-)) U4.14(ISNS(+))
N14805188: Q10.1(G) R58.2
N14810522: Q9.1(G) R57.2
N14810532: Q8.1(G) R56.2
N14814395: C70.1 R63.2
N14818963: J5.7 L8.1
N14818967: J5.8 L7.1
N14818971: J5.9 L6.1
N14901904: C69.1 R62.2
N15037743: C45.2 U4.8(SS)
N15077521: Q1.4(G) R1.2

Not connected (* = marked no-connect by the designer): D3 4(NC4)*; D4 4(NC4)*; D10 4(NC)*; D11 4(NC)*; D12 4(NC)*; SW1 4(SW1)*; U1 11(SYNC)*; U2 3(NC_0)* 5(NC_1)*

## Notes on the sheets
sheet 1
- COMPUTER GENERATED DRAWING.  DO NOT REVISE MANUALLY
- NOTES, UNLESS OTHERWISE SPECIFIED:
- REVISIONS
- REV
- DESCRIPTION
- DATE
- APPROVED
- 1. All components with designators "U", "D", "Y" and "Q" are electrostatic discharge sensitive.
  2. The letters DNI near a part mean "do not install".
- A
- Initial Release
- Aug 2017
- B
- Revision B
- Dec 2017
- C
- Revision C
- 3/22/2018
- IMPORTANT NOTICE
  Texas Instruments Incorporated and its subsidiaries (TI) reserve the right to make corrections, enhancements, improvements and other
  changes to its semiconductor products and services per JESD46, latest issue, and to discontinue any product or service per JESD48, latest
  issue. Buyers should obtain the latest relevant information before placing orders and should verify that such information is current and
  complete. All semiconductor products (also referred to herein as “components”) are sold subject to TI’s terms and conditions of sale
  supplied at the time of order acknowledgment.
  TI warrants performance of its components to the specifications applicable at the time of sale, in accordance with the warranty in TI’s terms
  and conditions of sale of semiconductor products. Testing and other quality control techniques are used to the extent TI deems necessary
  to support this warranty. Except where mandated by applicable law, testing of all parameters of each component is not necessarily
  performed.
  TI assumes no liability for applications assistance or the design of Buyers’ products. Buyers are responsible for their products and
  applications using TI components. To minimize the risks associated with Buyers’ products and applications, Buyers should provide
  adequate design and operating safeguards.
  TI does not warrant or represent that any license, either express or implied, is granted under any patent right, copyright, mask work right, or
  other intellectual property right relating to any combination, machine, or process in which TI components or services are used. Information
  published by TI regarding third-party products or services does not constitute a license to use such products or services or a warranty or
  endorsement thereof. Use of such information may require a license from a third party under the patents or other intellectual property of the
  third party, or a license from TI under the patents or other intellectual property of TI.
  Reproduction of significant portions of TI information in TI data books or data sheets is permissible only if reproduction is without alteration
  and is accompanied by all associated warranties, conditions, limitations, and notices. TI is not responsible or liable for such altered
  documentation. Information of third parties may be subject to additional restrictions.
  Resale of TI components or services with statements different from or beyond the parameters stated by TI for that component or service
  voids all express and any implied warranties for the associated TI component or service and is an unfair and deceptive business practice.
  TI is not responsible or liable for any such statements.
  Buyer acknowledges and agrees that it is solely responsible for compliance with all legal, regulatory and safety-related requirements
  concerning its products, and any use of TI components in its applications, notwithstanding any applications-related information or support
  that may be provided by TI. Buyer represents and agrees that it has all the necessary expertise to create and implement safeguards which
  anticipate dangerous consequences of failures, monitor failures and their consequences, lessen the likelihood of failures that might cause
  harm and take appropriate remedial actions. Buyer will fully indemnify TI and its representatives against any damages arising out of the use
  of any TI components in safety-critical applications.
  In some cases, TI components may be promoted specifically to facilitate safety-related applications. With such components, TI’s goal is to
  help enable customers to design and create their own end-product solutions that meet applicable functional safety standards and
  requirements. Nonetheless, such components are subject to these terms.
  No TI components are authorized for use in FDA Class III (or similar life-critical medical equipment) unless authorized officers of the parties
  have executed a special agreement specifically governing such use.
  Only those TI components which TI has specifically designated as military grade or “enhanced plastic” are designed and intended for use in
  military/aerospace applications or environments. Buyer acknowledges and agrees that any military or aerospace use of TI components
  which have not been so designated is solely at the Buyer's risk, and that Buyer is solely responsible for compliance with all legal and
  regulatory requirements in connection with such use.
  TI has specifically designated certain components as meeting ISO/TS16949 requirements, mainly for automotive use. In any case of use of
  non-designated products, TI will not be responsible for any failure to meet ISO/TS16949.
- 2515624
- TI Confidential - Selective Disclosure
sheet 2
- The three LED drivers can support a variety of LED
  configurations given that the total power (LED forward
  voltage drop, LED maximum current, efficiency, etc.)
  does not exceed 96W (16V, 6A max) delivered from the
  buck/boost pre-regulator.
  Note, each LED Driver can support a maximum of 8A
  output. The power and thermal ratings of the adjacent
  parts should also be taken into consideration.
sheet 3
- Battery Input Connector and Input Voltage Protection
- Power to Formatter Board
- 6V to 18V
  42V transients
- 80V
  60A
  5.8mohm
- 16V, 6A max
- 6V to 18V
  42V transients
- 60V
  80A
  4.5mohm
- 60V
  80A
  4.5mohm
- snubber
- 20V
  0.5A
- 20V
  1A
- 100V, 250mA
- 25A
  5.5mOhm
- The three LED drivers can support a variety of LED
  configurations given that the total power (LED forward
  voltage drop, LED maximum current, efficiency, etc.)
  does not exceed 96W (16V, 6A max) delivered from the
  buck/boost pre-regulator.
  Note, each LED Driver can support a maximum of 8A
  output. The power and thermal ratings of the adjacent
  parts should also be taken into consideration.
- 60V
  80A
  4.5mohm
- 60V
  80A
  4.5mohm
- snubber
- 60V
  3A
- 100V, 250mA
- 5W
- Input/Output Current Sense
  function disabled
- BOM
  Item\tQTY\tDNI\tReference\tPart Number\tManufacturer\tDescription\tValue\tPCB Footprint\tAEC\tTemp
  {Item}\t{Quantity}\t{DNI}\t{Reference}\t{Manuf Part Number}\t{Manufacturer}\t{Description}\t{Value}\t{PCB Footprint}\t{AEC}\t{Temp}
sheet 4
- The three LED drivers can support a variety of LED
  configurations given that the total power (LED forward
  voltage drop, LED maximum current, efficiency, etc.)
  does not exceed 96W (16V, 6A max) delivered from the
  buck/boost pre-regulator.
  Note, each LED Driver can support a maximum of 8A
  output. The power and thermal ratings of the adjacent
  parts should also be taken into consideration.
- 100mW
- 12V Turn-On
- 3.3V to 1.24V
- 100mW
- 3W
- NOT USED ON THIS BOARD
- 50A
  9mOhm
- HEADLIGHT
  DRIVER
  INTERFACE
- DNI output capacitor
- 4V, 8A max
- 20%
  12A
  37mOhm
- snubber
- snubber
- 10k pull-downs on each PMIC_LEDSEL pin.
- 45V
  15A
  0.48Vf
- Ferrites and capacitors to ground are
  for EMC reduction  if needed.
- 40V
  2A
  0.5Vf
- 40V
  15A
  27mOhm
- 12V Turn-On
- 100mW
- 3.3V to 1.24V
- 100mW
- 3W
- 50A
  9mOhm
- DNI output capacitor
- 4V, 8A max
- 20%
  12A
  37mOhm
- snubber
- snubber
- 45V
  15A
  0.48Vf
- 40V
  2A
  0.5Vf
- 40V
  15A
  27mOhm
- 100mW
- 12V UVLO
- 3.3V to 1.24V
- 100mW
- 3W
- 50A
  9mOhm
- DNI output capacitor
- 12V, 8A max
- 20%
  12A
  37mOhm
- snubber
- snubber
- 45V
  15A
  0.48Vf
- 40V
  2A
  0.5Vf
- 40V
  15A
  27mOhm
sheet 5
- 60V
  14A
  54mOhm
- Right-angle
  switch
- 12V, 1A max
- up to 3 fans
  (1A max total)
- 5A
  112mOhm
- 60V
  14A
  54mOhm
